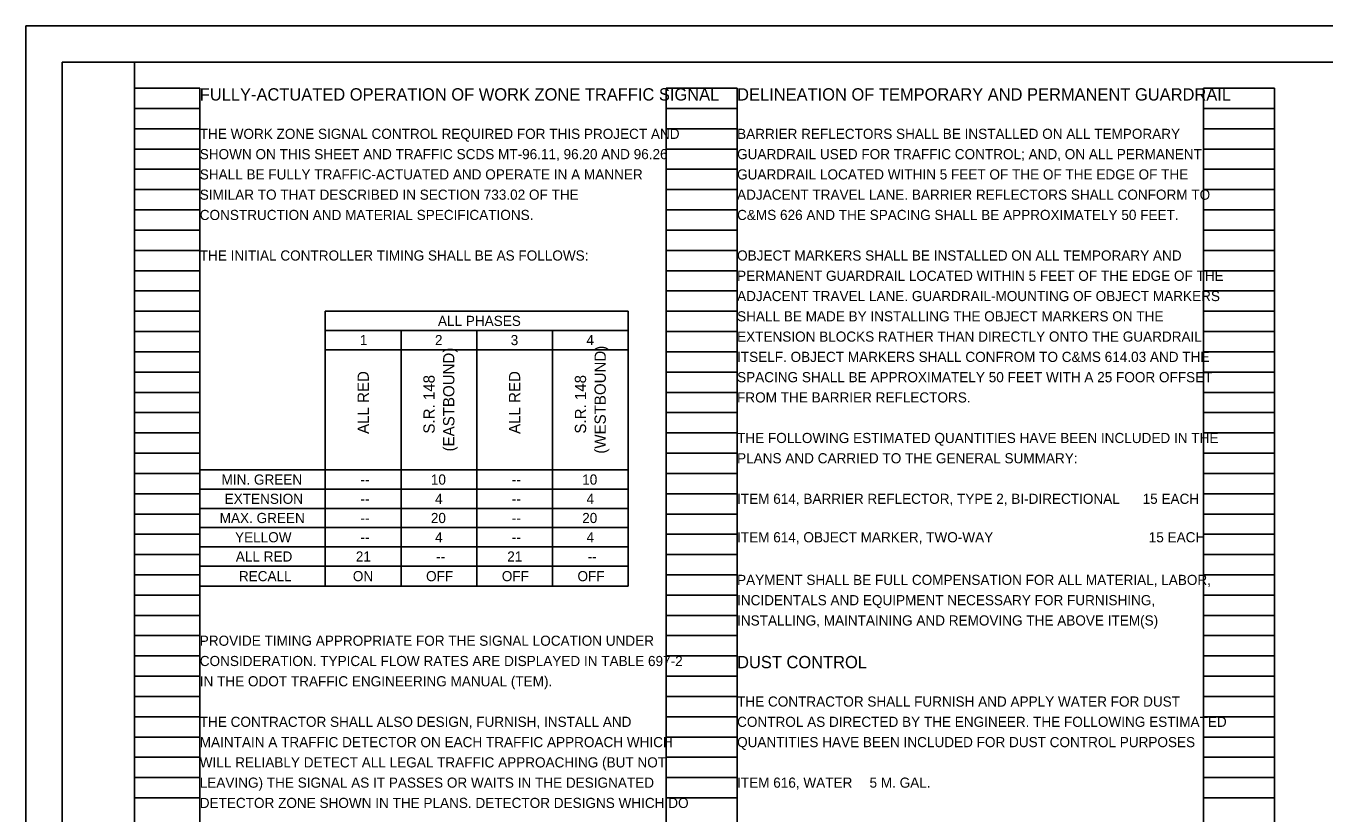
# Model space of a CAD drawing. Extents: x -18.3 to 50.3, y -3.1 to 38.9.
# Drawn here: x 0 to 17.93, y 11.13 to 22 of the extents above; entities that cross this region are included whole.
import ezdxf

# ---------------------------------------------------------------- set-up
doc = ezdxf.new("R2010")
doc.units = 0
for name, color, linetype in [('SH_Border', 7, 'Continuous'), ('SH_Cut_Line', 7, 'Continuous'), ('SH_Data', 7, 'Continuous'), ('SH_Text', 7, 'Continuous')]:
    doc.layers.add(name, color=color, linetype=linetype)

msp = doc.modelspace()

# ---------------------------------------------------------------- linework, layer by layer
at = {"layer": 'SH_Border'}
for points in [[(0.5, 21.5), (1.5, 21.5), (1.5, 0.5), (0.5, 0.5)], [(1.5, 21.5), (33.5, 21.5), (33.5, 0.5), (1.5, 0.5)]]:
    msp.add_lwpolyline(points, close=True, dxfattribs=at)
at = {"layer": 'SH_Cut_Line'}
msp.add_lwpolyline([(0, 0), (34, 0), (34, 22), (0, 22)], close=True, dxfattribs=at)
at = {"layer": 'SH_Data'}
for p, q in [((1.5, 0.98), (1.5, 21.14)), ((1.5, 21.14), (2.4, 21.14)), ((2.4, 0.98), (2.4, 21.14)), ((8.84, 0.98), (8.84, 21.14)), ((8.84, 21.14), (9.82, 21.14)), ((9.82, 0.98), (9.82, 21.14)), ((16.26, 0.98), (16.26, 21.14)), ((16.26, 21.14), (17.24, 21.14)), ((17.24, 0.98), (17.24, 21.14)), ((1.5, 20.86), (2.4, 20.86)), ((8.84, 20.86), (9.82, 20.86)), ((16.26, 20.86), (17.24, 20.86)), ((1.5, 20.58), (2.4, 20.58)), ((8.84, 20.58), (9.82, 20.58)), ((16.26, 20.58), (17.24, 20.58)), ((1.5, 20.3), (2.4, 20.3)), ((8.84, 20.3), (9.82, 20.3)), ((16.26, 20.3), (17.24, 20.3)), ((1.5, 20.02), (2.4, 20.02)), ((8.84, 20.02), (9.82, 20.02)), ((16.26, 20.02), (17.24, 20.02)), ((1.5, 19.74), (2.4, 19.74)), ((8.84, 19.74), (9.82, 19.74)), ((16.26, 19.74), (17.24, 19.74)), ((1.5, 19.46), (2.4, 19.46)), ((8.84, 19.46), (9.82, 19.46)), ((16.26, 19.46), (17.24, 19.46)), ((1.5, 19.18), (2.4, 19.18)), ((8.84, 19.18), (9.82, 19.18)), ((16.26, 19.18), (17.24, 19.18)), ((1.5, 18.9), (2.4, 18.9)), ((8.84, 18.9), (9.82, 18.9)), ((16.26, 18.9), (17.24, 18.9)), ((1.5, 18.62), (2.4, 18.62)), ((8.84, 18.62), (9.82, 18.62)), ((16.26, 18.62), (17.24, 18.62)), ((1.5, 18.34), (2.4, 18.34)), ((8.84, 18.34), (9.82, 18.34)), ((16.26, 18.34), (17.24, 18.34)), ((1.5, 18.06), (2.4, 18.06)), ((8.84, 18.06), (9.82, 18.06)), ((16.26, 18.06), (17.24, 18.06)), ((1.5, 17.78), (2.4, 17.78)), ((8.84, 17.78), (9.82, 17.78)), ((16.26, 17.78), (17.24, 17.78)), ((1.5, 17.5), (2.4, 17.5)), ((8.84, 17.5), (9.82, 17.5)), ((16.26, 17.5), (17.24, 17.5)), ((1.5, 17.22), (2.4, 17.22)), ((8.84, 17.22), (9.82, 17.22)), ((16.26, 17.22), (17.24, 17.22)), ((1.5, 16.94), (2.4, 16.94)), ((8.84, 16.94), (9.82, 16.94)), ((16.26, 16.94), (17.24, 16.94)), ((1.5, 16.66), (2.4, 16.66)), ((8.84, 16.66), (9.82, 16.66)), ((16.26, 16.66), (17.24, 16.66)), ((1.5, 16.38), (2.4, 16.38)), ((8.84, 16.38), (9.82, 16.38)), ((16.26, 16.38), (17.24, 16.38)), ((1.5, 16.1), (2.4, 16.1)), ((8.84, 16.1), (9.82, 16.1)), ((16.26, 16.1), (17.24, 16.1)), ((1.5, 15.82), (2.4, 15.82)), ((8.84, 15.82), (9.82, 15.82)), ((16.26, 15.82), (17.24, 15.82)), ((1.5, 15.54), (2.4, 15.54)), ((8.84, 15.54), (9.82, 15.54)), ((16.26, 15.54), (17.24, 15.54)), ((1.5, 15.26), (2.4, 15.26)), ((8.84, 15.26), (9.82, 15.26)), ((16.26, 15.26), (17.24, 15.26)), ((1.5, 14.98), (2.4, 14.98)), ((8.84, 14.98), (9.82, 14.98)), ((16.26, 14.98), (17.24, 14.98)), ((1.5, 14.7), (2.4, 14.7)), ((8.84, 14.7), (9.82, 14.7)), ((16.26, 14.7), (17.24, 14.7)), ((1.5, 14.42), (2.4, 14.42)), ((8.84, 14.42), (9.82, 14.42)), ((16.26, 14.42), (17.24, 14.42)), ((1.5, 14.14), (2.4, 14.14)), ((8.84, 14.14), (9.82, 14.14)), ((16.26, 14.14), (17.24, 14.14)), ((1.5, 13.86), (2.4, 13.86)), ((8.84, 13.86), (9.82, 13.86)), ((16.26, 13.86), (17.24, 13.86)), ((1.5, 13.58), (2.4, 13.58)), ((8.84, 13.58), (9.82, 13.58)), ((16.26, 13.58), (17.24, 13.58)), ((1.5, 13.3), (2.4, 13.3)), ((8.84, 13.3), (9.82, 13.3)), ((16.26, 13.3), (17.24, 13.3)), ((1.5, 13.02), (2.4, 13.02)), ((8.84, 13.02), (9.82, 13.02)), ((16.26, 13.02), (17.24, 13.02)), ((1.5, 12.74), (2.4, 12.74)), ((8.84, 12.74), (9.82, 12.74)), ((16.26, 12.74), (17.24, 12.74)), ((1.5, 12.46), (2.4, 12.46)), ((8.84, 12.46), (9.82, 12.46)), ((16.26, 12.46), (17.24, 12.46)), ((1.5, 12.18), (2.4, 12.18)), ((8.84, 12.18), (9.82, 12.18)), ((16.26, 12.18), (17.24, 12.18)), ((1.5, 11.9), (2.4, 11.9)), ((8.84, 11.9), (9.82, 11.9)), ((16.26, 11.9), (17.24, 11.9)), ((1.5, 11.62), (2.4, 11.62)), ((8.84, 11.62), (9.82, 11.62)), ((16.26, 11.62), (17.24, 11.62)), ((1.5, 11.34), (2.4, 11.34)), ((8.84, 11.34), (9.82, 11.34)), ((16.26, 11.34), (17.24, 11.34))]:
    msp.add_line(p, q, dxfattribs=at)
at = {"layer": 'SH_Text'}
for p, q in [((4.134, 18.06), (8.316, 18.06)), ((4.134, 18.06), (4.134, 17.794)), ((8.316, 18.06), (8.316, 17.794)), ((4.134, 17.794), (8.316, 17.794)), ((4.134, 17.794), (4.134, 17.529)), ((5.18, 17.794), (5.18, 17.529)), ((6.225, 17.794), (6.225, 17.529)), ((7.27, 17.794), (7.27, 17.529)), ((8.316, 17.794), (8.316, 17.529)), ((4.134, 17.529), (8.316, 17.529)), ((4.134, 17.529), (4.134, 15.869)), ((5.18, 17.529), (5.18, 15.869)), ((6.225, 17.529), (6.225, 15.869)), ((7.27, 17.529), (7.27, 15.869)), ((8.316, 17.529), (8.316, 15.869)), ((2.4, 15.869), (8.316, 15.869)), ((2.4, 15.869), (2.4, 15.603)), ((4.134, 15.869), (4.134, 15.603)), ((5.18, 15.869), (5.18, 15.603)), ((6.225, 15.869), (6.225, 15.603)), ((7.27, 15.869), (7.27, 15.603)), ((8.316, 15.869), (8.316, 15.603)), ((2.4, 15.603), (8.316, 15.603)), ((2.4, 15.603), (2.4, 15.337)), ((4.134, 15.603), (4.134, 15.337)), ((5.18, 15.603), (5.18, 15.337)), ((6.225, 15.603), (6.225, 15.337)), ((7.27, 15.603), (7.27, 15.337)), ((8.316, 15.603), (8.316, 15.337)), ((2.4, 15.337), (8.316, 15.337)), ((2.4, 15.337), (2.4, 15.072)), ((4.134, 15.337), (4.134, 15.072)), ((5.18, 15.337), (5.18, 15.072)), ((6.225, 15.337), (6.225, 15.072)), ((7.27, 15.337), (7.27, 15.072)), ((8.316, 15.337), (8.316, 15.072)), ((2.4, 15.072), (8.316, 15.072)), ((2.4, 15.072), (2.4, 14.806)), ((4.134, 15.072), (4.134, 14.806)), ((5.18, 15.072), (5.18, 14.806)), ((6.225, 15.072), (6.225, 14.806)), ((7.27, 15.072), (7.27, 14.806)), ((8.316, 15.072), (8.316, 14.806)), ((2.4, 14.806), (8.316, 14.806)), ((2.4, 14.806), (2.4, 14.541)), ((4.134, 14.806), (4.134, 14.541)), ((5.18, 14.806), (5.18, 14.541)), ((6.225, 14.806), (6.225, 14.541)), ((7.27, 14.806), (7.27, 14.541)), ((8.316, 14.806), (8.316, 14.541)), ((2.4, 14.541), (8.316, 14.541)), ((2.4, 14.541), (2.4, 14.264)), ((4.134, 14.541), (4.134, 14.264)), ((5.18, 14.541), (5.18, 14.264)), ((6.225, 14.541), (6.225, 14.264)), ((7.27, 14.541), (7.27, 14.264)), ((8.316, 14.541), (8.316, 14.264)), ((2.4, 14.264), (8.316, 14.264))]:
    msp.add_line(p, q, dxfattribs=at)

# ---------------------------------------------------------------- texts
for s, height, p in [('FULLY-ACTUATED OPERATION OF WORK ZONE TRAFFIC SIGNAL', 0.17, (2.4, 20.97)), ('DELINEATION OF TEMPORARY AND PERMANENT GUARDRAIL', 0.17, (9.82, 20.97)), ('THE WORK ZONE SIGNAL CONTROL REQUIRED FOR THIS PROJECT AND ', 0.14, (2.4, 20.44)), ('BARRIER REFLECTORS SHALL BE INSTALLED ON ALL TEMPORARY ', 0.14, (9.82, 20.44)), ('SHOWN ON THIS SHEET AND TRAFFIC SCDS MT-96.11, 96.20 AND 96.26 ', 0.14, (2.4, 20.16)), ('GUARDRAIL USED FOR TRAFFIC CONTROL; AND, ON ALL PERMANENT ', 0.14, (9.82, 20.16)), ('SHALL BE FULLY TRAFFIC-ACTUATED AND OPERATE IN A MANNER ', 0.14, (2.4, 19.88)), ('GUARDRAIL LOCATED WITHIN 5 FEET OF THE OF THE EDGE OF THE ', 0.14, (9.82, 19.88)), ('SIMILAR TO THAT DESCRIBED IN SECTION 733.02 OF THE ', 0.14, (2.4, 19.6)), ('ADJACENT TRAVEL LANE. BARRIER REFLECTORS SHALL CONFORM TO ', 0.14, (9.82, 19.6)), ('CONSTRUCTION AND MATERIAL SPECIFICATIONS.', 0.14, (2.4, 19.32)), ('C&MS 626 AND THE SPACING SHALL BE APPROXIMATELY 50 FEET. ', 0.14, (9.82, 19.32)), ('THE INITIAL CONTROLLER TIMING SHALL BE AS FOLLOWS:', 0.14, (2.4, 18.76)), ('OBJECT MARKERS SHALL BE INSTALLED ON ALL TEMPORARY AND ', 0.14, (9.82, 18.76)), ('PERMANENT GUARDRAIL LOCATED WITHIN 5 FEET OF THE EDGE OF THE ', 0.14, (9.82, 18.48)), ('ADJACENT TRAVEL LANE. GUARDRAIL-MOUNTING OF OBJECT MARKERS ', 0.14, (9.82, 18.2)), ('ALL PHASES', 0.14, (5.689, 17.857)), ('SHALL BE MADE BY INSTALLING THE OBJECT MARKERS ON THE ', 0.14, (9.82, 17.92)), ('EXTENSION BLOCKS RATHER THAN DIRECTLY ONTO THE GUARDRAIL ', 0.14, (9.82, 17.64)), ('1', 0.14, (4.61, 17.592)), ('2', 0.14, (5.648, 17.592)), ('3', 0.14, (6.694, 17.592)), ('4', 0.14, (7.739, 17.592)), ('ITSELF. OBJECT MARKERS SHALL CONFROM TO C&MS 614.03 AND THE ', 0.14, (9.82, 17.36)), ('SPACING SHALL BE APPROXIMATELY 50 FEET WITH A 25 FOOR OFFSET ', 0.14, (9.82, 17.08)), ('FROM THE BARRIER REFLECTORS.', 0.14, (9.82, 16.8)), ('THE FOLLOWING ESTIMATED QUANTITIES HAVE BEEN INCLUDED IN THE ', 0.14, (9.82, 16.24)), ('PLANS AND CARRIED TO THE GENERAL SUMMARY:', 0.14, (9.82, 15.96)), ('MIN. GREEN', 0.14, (2.701, 15.666)), ('10', 0.14, (5.591, 15.666)), ('10', 0.14, (7.681, 15.666)), (' --', 0.14, (4.567, 15.666)), (' --', 0.14, (6.658, 15.666)), ('EXTENSION', 0.14, (2.744, 15.4)), (' --', 0.14, (4.567, 15.4)), ('4', 0.14, (5.65, 15.4)), (' --', 0.14, (6.658, 15.4)), ('4', 0.14, (7.741, 15.4)), ('ITEM 614, BARRIER REFLECTOR, TYPE 2, BI-DIRECTIONAL', 0.14, (9.82, 15.4)), ('15 EACH', 0.14, (15.42, 15.4)), ('MAX. GREEN', 0.14, (2.675, 15.135)), ('20', 0.14, (5.591, 15.135)), ('20', 0.14, (7.681, 15.135)), (' --', 0.14, (4.567, 15.135)), (' --', 0.14, (6.658, 15.135)), ('YELLOW', 0.14, (2.887, 14.869)), (' --', 0.14, (4.567, 14.869)), ('4', 0.14, (5.65, 14.869)), (' --', 0.14, (6.658, 14.869)), ('4', 0.14, (7.741, 14.869)), ('ITEM 614, OBJECT MARKER, TWO-WAY      ', 0.14, (9.82, 14.869)), ('                                     15 EACH', 0.14, (13.58, 14.869)), ('ALL RED', 0.14, (2.898, 14.603)), ('21', 0.14, (4.555, 14.603)), ('21', 0.14, (6.646, 14.603)), (' --', 0.14, (5.613, 14.603)), (' --', 0.14, (7.704, 14.603)), ('RECALL', 0.14, (2.94, 14.332)), ('ON', 0.14, (4.514, 14.332)), ('OFF', 0.14, (5.525, 14.332)), ('OFF', 0.14, (6.571, 14.332)), ('OFF', 0.14, (7.616, 14.332)), ('PAYMENT SHALL BE FULL COMPENSATION FOR ALL MATERIAL, LABOR, ', 0.14, (9.82, 14.28)), ('INCIDENTALS AND EQUIPMENT NECESSARY FOR FURNISHING, ', 0.14, (9.82, 14)), ('INSTALLING, MAINTAINING AND REMOVING THE ABOVE ITEM(S)', 0.14, (9.82, 13.72)), ('PROVIDE TIMING APPROPRIATE FOR THE SIGNAL LOCATION UNDER ', 0.14, (2.4, 13.44)), ('CONSIDERATION. TYPICAL FLOW RATES ARE DISPLAYED IN TABLE 697-2 ', 0.14, (2.4, 13.16)), ('DUST CONTROL', 0.17, (9.82, 13.13)), ('IN THE ODOT TRAFFIC ENGINEERING MANUAL (TEM).', 0.14, (2.4, 12.88)), ('THE CONTRACTOR SHALL FURNISH AND APPLY WATER FOR DUST ', 0.14, (9.82, 12.6)), ('THE CONTRACTOR SHALL ALSO DESIGN, FURNISH, INSTALL AND ', 0.14, (2.4, 12.32)), ('CONTROL AS DIRECTED BY THE ENGINEER. THE FOLLOWING ESTIMATED ', 0.14, (9.82, 12.32)), ('MAINTAIN A TRAFFIC DETECTOR ON EACH TRAFFIC APPROACH WHICH ', 0.14, (2.4, 12.04)), ('QUANTITIES HAVE BEEN INCLUDED FOR DUST CONTROL PURPOSES', 0.14, (9.82, 12.04)), ('WILL RELIABLY DETECT ALL LEGAL TRAFFIC APPROACHING (BUT NOT ', 0.14, (2.4, 11.76)), ('LEAVING) THE SIGNAL AS IT PASSES OR WAITS IN THE DESIGNATED ', 0.14, (2.4, 11.48)), ('ITEM 616, WATER     ', 0.14, (9.82, 11.48)), ('5 M. GAL.', 0.14, (11.649, 11.48)), ('DETECTOR ZONE SHOWN IN THE PLANS. DETECTOR DESIGNS WHICH DO ', 0.14, (2.4, 11.2))]:
    msp.add_text(s, height=height, dxfattribs=at).set_placement(p)
for s, height, p in [('(WESTBOUND)', 0.15558, (8.007, 16.093)), ('(EASTBOUND)', 0.15558, (5.916, 16.124)), ('ALL RED', 0.1556, (4.735, 16.366)), ('ALL RED', 0.1556, (6.825, 16.366)), ('S.R. 148', 0.1556, (5.644, 16.37)), ('S.R. 148', 0.1556, (7.735, 16.37))]:
    msp.add_text(s, height=height, rotation=90, dxfattribs=at).set_placement(p)

doc.saveas('drawing.dxf')
